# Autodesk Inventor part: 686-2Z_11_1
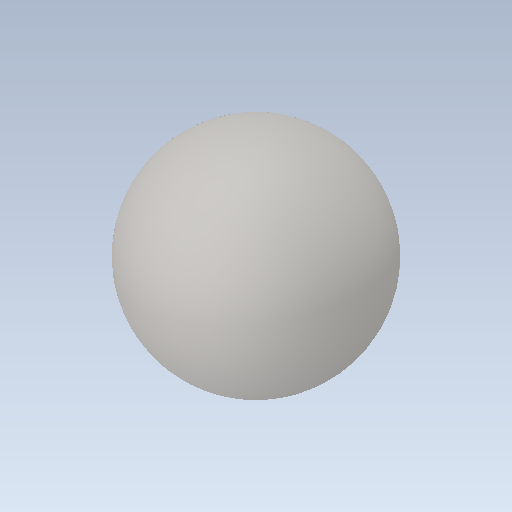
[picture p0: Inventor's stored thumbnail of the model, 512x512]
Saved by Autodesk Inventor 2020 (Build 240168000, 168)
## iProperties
Created: 2017-11
Part Number: 686-2Z_11_1
Material: Ogólny
Document SubType Name: Modeling
Designer: Tomasz
Density: 1 g/cm^3
Appearance: Domyślna
Sending System: SolidWorks 2017
Last Author: Tomasz
Last Saved: 2017-11-19
Source: 686-2Z_11_1
Author: Tomasz
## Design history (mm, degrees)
feature "Imported1"
node "Bryła1"
